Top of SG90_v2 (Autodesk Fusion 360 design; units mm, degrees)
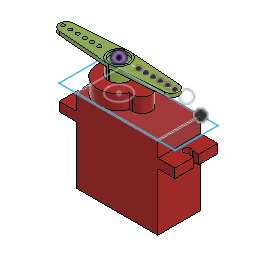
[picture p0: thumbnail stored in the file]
component_insert "Component Insert"
sketch "Sketch1" plane through (0, 0, 22.7) normal (0, 0, 1) x axis (-1, 0, 0)
  line L1 (-0.95, -2.5) -> (0.0058, -2.5)
  line L2 (0.0058, 2.5) -> (-0.95, 2.5)
  line L3 (-11.25, 5.9) -> (5.35, 5.9)
  line L4 (-11.25, -5.9) -> (-11.25, 5.9)
  line L5 (5.35, -5.9) -> (-11.25, -5.9)
  line L6 (11.25, -5.9) -> (-11.25, -5.9)
  line L7 (11.25, 5.9) -> (11.25, -5.9)
  line L8 (-11.25, 5.9) -> (11.25, 5.9)
  line L9 (-11.25, -5.9) -> (-11.25, 5.9)
  line L10 (-16.0236, -5.9) -> (15.9764, -5.9)
  line L11 (-16.0236, 5.9) -> (-16.0236, -5.9)
  line L12 (15.9764, 5.9) -> (-16.0236, 5.9)
  line L13 (15.9764, -5.9) -> (15.9764, 5.9)
  arc A1 centre (5.35, 0) radius 5.9 clockwise from (5.35, -5.9) to (0.0058, -2.5)
  arc A2 centre (-0.95, 0) radius 2.5 clockwise from (-0.95, -2.5) to (-0.95, 2.5)
  arc A3 centre (5.35, 0) radius 5.9 clockwise from (0.0058, 2.5) to (5.35, 5.9)
  circle C1 centre (5.35, 0) radius 2.95
  point P11 (-11.25, -5.9)
  point P13 (-11.25, -5.9)
  point P14 (11.25, -5.9)
  point P16 (-11.25, 5.9)
  point P17 (15.9764, -5.9)
  point P18 (-16.0236, -5.9)
  point P20 (15.9764, 5.9)
  concentric A1 C1
  horizontal L6
  vertical L7
  horizontal L8
  vertical L9
  coincident P11 P13
  horizontal L10
  vertical L11
  horizontal L12
  vertical L13
  dimension "d1" diameter C1 = 5.9
  dimension "d2" distance P13 P14 = 22.5
  dimension "d3" distance P13 P16 = 11.8
  dimension "d4" distance P17 P18 = 32
  dimension "d5" distance P17 P20 = 11.8
sketch "Sketch4" plane through (0, 0, 31.2) normal (0, 0, 1) x axis (-1, 0, 0)
  line L1 (19.85, -1.8997) -> (5.35, -3)
  line L2 (5.35, 3) -> (19.85, 1.8997)
  circle C1 centre (16.75, 0) radius 0.5
  circle C2 centre (10.75, 0) radius 0.5
  circle C3 centre (18.75, 0) radius 0.5
  circle C4 centre (14.75, 0) radius 0.5
  circle C5 centre (12.75, 0) radius 0.5
  circle C6 centre (20.75, 0) radius 0.5
  circle C7 centre (5.35, 0) radius 2.5
  arc A1 centre (19.85, 0) radius 1.8997 clockwise from (19.85, 1.8997) to (19.85, -1.8997)
  arc A2 centre (5.35, 0) radius 3 clockwise from (5.35, -3) to (5.35, 3)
